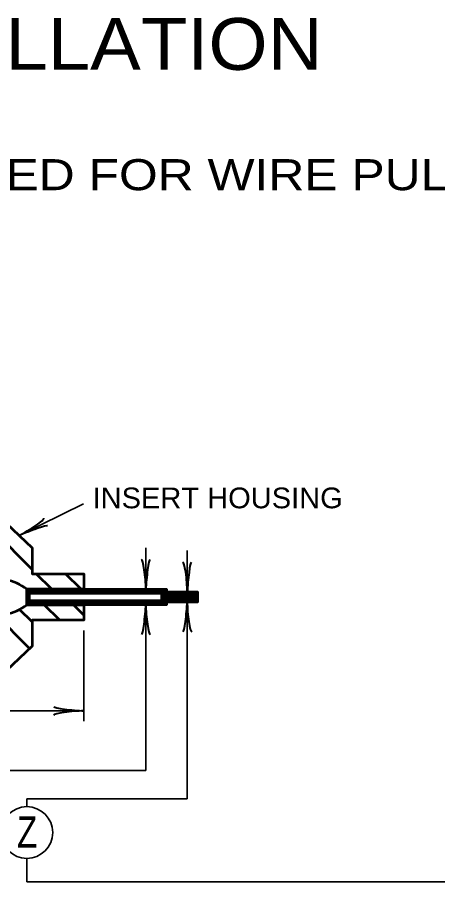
# Model space of a CAD drawing. Extents: x -1 to 679, y 0 to 440.
# Drawn here: x 139.2 to 179.8, y 135.8 to 219.2 of the extents above; entities that cross this region are included whole.
import ezdxf
from ezdxf.enums import TextEntityAlignment as Align

# ---------------------------------------------------------------- set-up
doc = ezdxf.new("R2010")
doc.units = 0
doc.header["$LTSCALE"] = 0.8
doc.layers.add('1', color=7, linetype='Continuous', lineweight=53)

msp = doc.modelspace()

# ---------------------------------------------------------------- linework, layer by layer
at = {"layer": '1', "lineweight": 35}
for p, q in [((139.3878, 169.1993), (145.6044, 172.2589)), ((151.6378, 164.0118), (151.6378, 168.0118)), ((155.6378, 163.7618), (155.6378, 167.7618)), ((151.6378, 162.5118), (151.6378, 146.5118)), ((155.6378, 162.7618), (155.6378, 143.7618)), ((145.6378, 160.0118), (145.6378, 151.2618)), ((122.6378, 152.2618), (145.6378, 152.2618)), ((151.6378, 146.5118), (134.6378, 146.5118)), ((155.6378, 143.7618), (140.1378, 143.7618)), ((140.1378, 143.7618), (140.1378, 143.0118)), ((140.1378, 138.0118), (140.1378, 135.7618)), ((140.1378, 135.7618), (223.051, 135.7618))]:
    msp.add_line(p, q, dxfattribs=at)
at = {"layer": '1'}
for p, q in [((140.6378, 165.9284), (136.1795, 170.3868)), ((142.5545, 164.0118), (141.0545, 165.5118)), ((145.3829, 164.0118), (143.8829, 165.5118)), ((140.1378, 164.0118), (145.6378, 164.0118)), ((140.1378, 163.9463), (140.2032, 164.0118)), ((140.1378, 163.8049), (140.3447, 164.0118)), ((140.1378, 163.6635), (140.4861, 164.0118)), ((140.1378, 163.5221), (140.6275, 164.0118)), ((140.4722, 163.6368), (140.1378, 163.9711)), ((140.3878, 163.5797), (140.1378, 163.8297)), ((140.3878, 163.4382), (140.1378, 163.6882)), ((140.1378, 163.3807), (140.3878, 163.6307)), ((140.6136, 163.6368), (140.2386, 164.0118)), ((140.755, 163.6368), (140.38, 164.0118)), ((140.3939, 163.6368), (140.7689, 164.0118)), ((140.8965, 163.6368), (140.5215, 164.0118)), ((140.5353, 163.6368), (140.9103, 164.0118)), ((141.0379, 163.6368), (140.6629, 164.0118)), ((140.6768, 163.6368), (141.0518, 164.0118)), ((141.1793, 163.6368), (140.8043, 164.0118)), ((140.8183, 163.6368), (141.1933, 164.0118)), ((141.3208, 163.6368), (140.9458, 164.0118)), ((140.9597, 163.6368), (141.3347, 164.0118)), ((141.4622, 163.6368), (141.0872, 164.0118)), ((141.1011, 163.6368), (141.4761, 164.0118)), ((141.6036, 163.6368), (141.2286, 164.0118)), ((141.2425, 163.6368), (141.6175, 164.0118)), ((141.745, 163.6368), (141.37, 164.0118)), ((141.3839, 163.6368), (141.7589, 164.0118)), ((141.8864, 163.6368), (141.5114, 164.0118)), ((141.5253, 163.6368), (141.9003, 164.0118)), ((142.0278, 163.6368), (141.6528, 164.0118)), ((141.6668, 163.6368), (142.0418, 164.0118)), ((142.1693, 163.6368), (141.7943, 164.0118)), ((141.8082, 163.6368), (142.1832, 164.0118)), ((142.3107, 163.6368), (141.9357, 164.0118)), ((141.9496, 163.6368), (142.3246, 164.0118)), ((142.4521, 163.6368), (142.0771, 164.0118)), ((142.091, 163.6368), (142.466, 164.0118)), ((142.5935, 163.6368), (142.2185, 164.0118)), ((142.2324, 163.6368), (142.6074, 164.0118)), ((142.7349, 163.6368), (142.3599, 164.0118)), ((142.3738, 163.6368), (142.7488, 164.0118)), ((142.8763, 163.6368), (142.5013, 164.0118)), ((142.5153, 163.6368), (142.8903, 164.0118)), ((143.0178, 163.6368), (142.6428, 164.0118)), ((142.6567, 163.6368), (143.0317, 164.0118)), ((143.1592, 163.6368), (142.7842, 164.0118)), ((142.7981, 163.6368), (143.1731, 164.0118)), ((143.3006, 163.6368), (142.9256, 164.0118)), ((142.9395, 163.6368), (143.3145, 164.0118)), ((143.4421, 163.6368), (143.0671, 164.0118)), ((143.081, 163.6368), (143.456, 164.0118)), ((143.5835, 163.6368), (143.2085, 164.0118)), ((143.2224, 163.6368), (143.5974, 164.0118)), ((143.7249, 163.6368), (143.3499, 164.0118)), ((143.3638, 163.6368), (143.7388, 164.0118)), ((143.8663, 163.6368), (143.4913, 164.0118)), ((143.5052, 163.6368), (143.8802, 164.0118)), ((144.0077, 163.6368), (143.6327, 164.0118)), ((143.6467, 163.6368), (144.0217, 164.0118)), ((144.1492, 163.6368), (143.7742, 164.0118)), ((143.7881, 163.6368), (144.1631, 164.0118)), ((144.2906, 163.6368), (143.9156, 164.0118)), ((143.9295, 163.6368), (144.3045, 164.0118)), ((144.432, 163.6368), (144.057, 164.0118)), ((144.0709, 163.6368), (144.4459, 164.0118)), ((144.5734, 163.6368), (144.1984, 164.0118)), ((144.2123, 163.6368), (144.5873, 164.0118)), ((144.7148, 163.6368), (144.3398, 164.0118)), ((144.3537, 163.6368), (144.7287, 164.0118)), ((144.8562, 163.6368), (144.4812, 164.0118)), ((144.4952, 163.6368), (144.8702, 164.0118)), ((144.9977, 163.6368), (144.6227, 164.0118)), ((144.6366, 163.6368), (145.0116, 164.0118)), ((145.1391, 163.6368), (144.7641, 164.0118)), ((144.778, 163.6368), (145.153, 164.0118)), ((145.2805, 163.6368), (144.9055, 164.0118)), ((144.9194, 163.6368), (145.2944, 164.0118)), ((145.4219, 163.6368), (145.0469, 164.0118)), ((145.0608, 163.6368), (145.4358, 164.0118)), ((145.5633, 163.6368), (145.1883, 164.0118)), ((145.2022, 163.6368), (145.5772, 164.0118)), ((145.7047, 163.6368), (145.3297, 164.0118)), ((145.3437, 163.6368), (145.7187, 164.0118)), ((145.8462, 163.6368), (145.4712, 164.0118)), ((145.4851, 163.6368), (145.8601, 164.0118)), ((145.9877, 163.6368), (145.6127, 164.0118)), ((145.6266, 163.6368), (146.0016, 164.0118)), ((146.1291, 163.6368), (145.7541, 164.0118)), ((145.768, 163.6368), (146.143, 164.0118)), ((146.2705, 163.6368), (145.8955, 164.0118)), ((145.9094, 163.6368), (146.2844, 164.0118)), ((146.4119, 163.6368), (146.0369, 164.0118)), ((146.0508, 163.6368), (146.4258, 164.0118)), ((146.5533, 163.6368), (146.1783, 164.0118)), ((146.1923, 163.6368), (146.5673, 164.0118)), ((146.6947, 163.6368), (146.3197, 164.0118)), ((146.3337, 163.6368), (146.7087, 164.0118)), ((146.8362, 163.6368), (146.4612, 164.0118)), ((146.4751, 163.6368), (146.8501, 164.0118)), ((146.9776, 163.6368), (146.6026, 164.0118)), ((146.6165, 163.6368), (146.9915, 164.0118)), ((147.119, 163.6368), (146.744, 164.0118)), ((146.7579, 163.6368), (147.1329, 164.0118)), ((147.2604, 163.6368), (146.8854, 164.0118)), ((146.8993, 163.6368), (147.2743, 164.0118)), ((147.4018, 163.6368), (147.0268, 164.0118)), ((147.0408, 163.6368), (147.4158, 164.0118)), ((147.5433, 163.6368), (147.1683, 164.0118)), ((147.1822, 163.6368), (147.5572, 164.0118)), ((147.6847, 163.6368), (147.3097, 164.0118)), ((147.3236, 163.6368), (147.6986, 164.0118)), ((147.8261, 163.6368), (147.4511, 164.0118)), ((147.465, 163.6368), (147.84, 164.0118)), ((147.9675, 163.6368), (147.5925, 164.0118)), ((147.6064, 163.6368), (147.9814, 164.0118)), ((148.1089, 163.6368), (147.7339, 164.0118)), ((147.7478, 163.6368), (148.1228, 164.0118)), ((148.2503, 163.6368), (147.8753, 164.0118)), ((147.8893, 163.6368), (148.2643, 164.0118)), ((148.3918, 163.6368), (148.0168, 164.0118)), ((148.0307, 163.6368), (148.4057, 164.0118)), ((148.5332, 163.6368), (148.1582, 164.0118)), ((148.1722, 163.6368), (148.5472, 164.0118)), ((148.6747, 163.6368), (148.2997, 164.0118)), ((148.3136, 163.6368), (148.6886, 164.0118)), ((148.8161, 163.6368), (148.4411, 164.0118)), ((148.455, 163.6368), (148.83, 164.0118)), ((148.9575, 163.6368), (148.5825, 164.0118)), ((148.5964, 163.6368), (148.9714, 164.0118)), ((149.0989, 163.6368), (148.7239, 164.0118)), ((148.7378, 163.6368), (149.1128, 164.0118)), ((149.2403, 163.6368), (148.8653, 164.0118)), ((148.8792, 163.6368), (149.2542, 164.0118)), ((149.3817, 163.6368), (149.0067, 164.0118)), ((149.0207, 163.6368), (149.3957, 164.0118)), ((149.5232, 163.6368), (149.1482, 164.0118)), ((149.1621, 163.6368), (149.5371, 164.0118)), ((149.6646, 163.6368), (149.2896, 164.0118)), ((149.3035, 163.6368), (149.6785, 164.0118)), ((149.806, 163.6368), (149.431, 164.0118)), ((149.4449, 163.6368), (149.8199, 164.0118)), ((149.9474, 163.6368), (149.5724, 164.0118)), ((149.5863, 163.6368), (149.9613, 164.0118)), ((150.0888, 163.6368), (149.7138, 164.0118)), ((149.7277, 163.6368), (150.1027, 164.0118)), ((150.2302, 163.6368), (149.8552, 164.0118)), ((149.8692, 163.6368), (150.2442, 164.0118)), ((150.3717, 163.6368), (149.9967, 164.0118)), ((150.0106, 163.6368), (150.3856, 164.0118)), ((150.5131, 163.6368), (150.1381, 164.0118)), ((150.152, 163.6368), (150.527, 164.0118)), ((150.6545, 163.6368), (150.2795, 164.0118)), ((150.2934, 163.6368), (150.6684, 164.0118)), ((150.7959, 163.6368), (150.4209, 164.0118)), ((150.4348, 163.6368), (150.8098, 164.0118)), ((150.9374, 163.6368), (150.5624, 164.0118)), ((150.5762, 163.6368), (150.9512, 164.0118)), ((151.0788, 163.6368), (150.7038, 164.0118)), ((150.7177, 163.6368), (151.0927, 164.0118)), ((151.2202, 163.6368), (150.8452, 164.0118)), ((150.8592, 163.6368), (151.2342, 164.0118)), ((151.3617, 163.6368), (150.9867, 164.0118)), ((151.0006, 163.6368), (151.3756, 164.0118)), ((151.5031, 163.6368), (151.1281, 164.0118)), ((151.142, 163.6368), (151.517, 164.0118)), ((151.6445, 163.6368), (151.2695, 164.0118)), ((151.2834, 163.6368), (151.6584, 164.0118)), ((151.7859, 163.6368), (151.4109, 164.0118)), ((151.4248, 163.6368), (151.7998, 164.0118)), ((151.9273, 163.6368), (151.5523, 164.0118)), ((151.5662, 163.6368), (151.9412, 164.0118)), ((152.0687, 163.6368), (151.6937, 164.0118)), ((151.7077, 163.6368), (152.0827, 164.0118)), ((152.2102, 163.6368), (151.8352, 164.0118)), ((151.8491, 163.6368), (152.2241, 164.0118)), ((152.3516, 163.6368), (151.9766, 164.0118)), ((151.9905, 163.6368), (152.3655, 164.0118)), ((152.493, 163.6368), (152.118, 164.0118)), ((152.1319, 163.6368), (152.5069, 164.0118)), ((152.6344, 163.6368), (152.2594, 164.0118)), ((152.2733, 163.6368), (152.6483, 164.0118)), ((152.7758, 163.6368), (152.4008, 164.0118)), ((152.4147, 163.6368), (152.7897, 164.0118)), ((152.9172, 163.6368), (152.5422, 164.0118)), ((152.5562, 163.6368), (152.9312, 164.0118)), ((153.0587, 163.6368), (152.6837, 164.0118)), ((152.6976, 163.6368), (153.0726, 164.0118)), ((154.0751, 162.7618), (152.8251, 164.0118)), ((152.839, 163.6368), (153.214, 164.0118)), ((152.8454, 162.5118), (154.0954, 163.7618)), ((154.2165, 162.7618), (152.9665, 164.0118)), ((152.9804, 163.6368), (153.3554, 164.0118)), ((152.9868, 162.5118), (154.2368, 163.7618)), ((154.358, 162.7618), (153.108, 164.0118)), ((153.1219, 163.6368), (153.4969, 164.0118)), ((153.1283, 162.5118), (154.3783, 163.7618)), ((153.1378, 163.5112), (153.6378, 164.0112)), ((153.1378, 163.3698), (153.6378, 163.8698)), ((153.1378, 163.2284), (153.6712, 163.7618)), ((153.1378, 163.087), (153.8126, 163.7618)), ((153.1378, 162.9456), (153.954, 163.7618)), ((154.4994, 162.7618), (153.2494, 164.0118)), ((153.2697, 162.5118), (154.5197, 163.7618)), ((153.6378, 163.7647), (153.3908, 164.0118)), ((153.6378, 163.9062), (153.5323, 164.0118)), ((154.6408, 162.7618), (153.6408, 163.7618)), ((153.6611, 162.7618), (154.6611, 163.7618)), ((154.7823, 162.7618), (153.7823, 163.7618)), ((153.8025, 162.7618), (154.8025, 163.7618)), ((154.9237, 162.7618), (153.9237, 163.7618)), ((153.9439, 162.7618), (154.9439, 163.7618)), ((155.0651, 162.7618), (154.0651, 163.7618)), ((154.0853, 162.7618), (155.0853, 163.7618)), ((155.2065, 162.7618), (154.2065, 163.7618)), ((154.2267, 162.7618), (155.2267, 163.7618)), ((155.3479, 162.7618), (154.3479, 163.7618)), ((154.3682, 162.7618), (155.3682, 163.7618)), ((155.4893, 162.7618), (154.4893, 163.7618)), ((154.5096, 162.7618), (155.5096, 163.7618)), ((155.6308, 162.7618), (154.6308, 163.7618)), ((154.651, 162.7618), (155.651, 163.7618)), ((155.7722, 162.7618), (154.7722, 163.7618)), ((154.7925, 162.7618), (155.7925, 163.7618)), ((155.9136, 162.7618), (154.9136, 163.7618)), ((154.9339, 162.7618), (155.9339, 163.7618)), ((156.055, 162.7618), (155.055, 163.7618)), ((155.0753, 162.7618), (156.0753, 163.7618)), ((156.1964, 162.7618), (155.1964, 163.7618)), ((155.2167, 162.7618), (156.2167, 163.7618)), ((156.3378, 162.7618), (155.3378, 163.7618)), ((155.3582, 162.7618), (156.3582, 163.7618)), ((156.4793, 162.7618), (155.4793, 163.7618)), ((155.4996, 162.7618), (156.4996, 163.7618)), ((156.6207, 162.7618), (155.6207, 163.7618)), ((155.641, 162.7618), (156.6378, 163.7586)), ((156.6378, 162.886), (155.7621, 163.7618)), ((156.6378, 163.0275), (155.9036, 163.7618)), ((156.6378, 163.1689), (156.045, 163.7618)), ((156.6378, 163.3103), (156.1864, 163.7618)), ((156.6378, 163.4518), (156.3278, 163.7618)), ((156.6378, 163.5932), (156.4692, 163.7618)), ((156.6378, 163.7346), (156.6107, 163.7618)), ((140.3878, 163.2968), (140.1378, 163.5468)), ((140.1378, 163.2392), (140.3878, 163.4892)), ((140.3878, 163.1554), (140.1378, 163.4054)), ((140.1378, 163.0977), (140.3878, 163.3477)), ((140.3878, 163.014), (140.1378, 163.264)), ((140.1378, 162.9563), (140.3878, 163.2063)), ((140.7487, 162.5118), (140.1378, 163.1226)), ((140.1378, 162.8149), (140.3878, 163.0649)), ((140.6072, 162.5118), (140.1378, 162.9812)), ((140.1378, 162.6735), (140.3878, 162.9235)), ((140.1378, 162.5321), (140.4925, 162.8868)), ((140.4658, 162.5118), (140.1378, 162.8397)), ((140.2589, 162.5118), (140.6339, 162.8868)), ((140.4003, 162.5118), (140.7753, 162.8868)), ((140.8901, 162.5118), (140.5151, 162.8868)), ((140.5418, 162.5118), (140.9168, 162.8868)), ((141.0315, 162.5118), (140.6565, 162.8868)), ((140.6832, 162.5118), (141.0582, 162.8868)), ((141.1729, 162.5118), (140.7979, 162.8868)), ((140.8246, 162.5118), (141.1996, 162.8868)), ((141.3143, 162.5118), (140.9393, 162.8868)), ((140.966, 162.5118), (141.341, 162.8868)), ((141.4557, 162.5118), (141.0807, 162.8868)), ((141.1074, 162.5118), (141.4824, 162.8868)), ((141.5972, 162.5118), (141.2222, 162.8868)), ((141.2488, 162.5118), (141.6238, 162.8868)), ((141.7386, 162.5118), (141.3636, 162.8868)), ((141.3903, 162.5118), (141.7653, 162.8868)), ((141.88, 162.5118), (141.505, 162.8868)), ((141.5317, 162.5118), (141.9067, 162.8868)), ((142.0215, 162.5118), (141.6465, 162.8868)), ((141.6731, 162.5118), (142.0481, 162.8868)), ((142.1629, 162.5118), (141.7879, 162.8868)), ((141.8145, 162.5118), (142.1895, 162.8868)), ((142.3043, 162.5118), (141.9293, 162.8868)), ((141.956, 162.5118), (142.331, 162.8868)), ((142.4458, 162.5118), (142.0708, 162.8868)), ((142.0974, 162.5118), (142.4724, 162.8868)), ((142.5872, 162.5118), (142.2122, 162.8868)), ((142.2388, 162.5118), (142.6138, 162.8868)), ((142.7286, 162.5118), (142.3536, 162.8868)), ((142.3802, 162.5118), (142.7552, 162.8868)), ((142.87, 162.5118), (142.495, 162.8868)), ((142.5217, 162.5118), (142.8967, 162.8868)), ((143.0114, 162.5118), (142.6364, 162.8868)), ((142.6631, 162.5118), (143.0381, 162.8868)), ((143.1528, 162.5118), (142.7778, 162.8868)), ((142.8045, 162.5118), (143.1795, 162.8868)), ((143.2943, 162.5118), (142.9193, 162.8868)), ((142.9459, 162.5118), (143.3209, 162.8868)), ((143.4357, 162.5118), (143.0607, 162.8868)), ((143.0873, 162.5118), (143.4623, 162.8868)), ((143.5771, 162.5118), (143.2021, 162.8868)), ((143.2287, 162.5118), (143.6037, 162.8868)), ((143.7185, 162.5118), (143.3435, 162.8868)), ((143.3702, 162.5118), (143.7452, 162.8868)), ((143.8599, 162.5118), (143.4849, 162.8868)), ((143.5116, 162.5118), (143.8866, 162.8868)), ((144.0013, 162.5118), (143.6263, 162.8868)), ((143.653, 162.5118), (144.028, 162.8868)), ((144.1428, 162.5118), (143.7678, 162.8868)), ((143.7944, 162.5118), (144.1694, 162.8868)), ((144.2842, 162.5118), (143.9092, 162.8868)), ((143.9358, 162.5118), (144.3108, 162.8868)), ((144.4256, 162.5118), (144.0506, 162.8868)), ((144.0772, 162.5118), (144.4522, 162.8868)), ((144.5671, 162.5118), (144.1921, 162.8868)), ((144.2187, 162.5118), (144.5937, 162.8868)), ((144.7085, 162.5118), (144.3335, 162.8868)), ((144.3601, 162.5118), (144.7351, 162.8868)), ((144.8499, 162.5118), (144.4749, 162.8868)), ((144.5016, 162.5118), (144.8766, 162.8868)), ((144.9913, 162.5118), (144.6163, 162.8868)), ((144.643, 162.5118), (145.018, 162.8868)), ((145.1327, 162.5118), (144.7577, 162.8868)), ((144.7844, 162.5118), (145.1594, 162.8868)), ((145.2742, 162.5118), (144.8992, 162.8868)), ((144.9258, 162.5118), (145.3008, 162.8868)), ((145.4156, 162.5118), (145.0406, 162.8868)), ((145.0673, 162.5118), (145.4423, 162.8868)), ((145.557, 162.5118), (145.182, 162.8868)), ((145.2087, 162.5118), (145.5837, 162.8868)), ((145.6984, 162.5118), (145.3234, 162.8868)), ((145.3501, 162.5118), (145.7251, 162.8868)), ((145.8398, 162.5118), (145.4648, 162.8868)), ((145.4915, 162.5118), (145.8665, 162.8868)), ((145.9812, 162.5118), (145.6062, 162.8868)), ((145.6329, 162.5118), (146.0079, 162.8868)), ((146.1227, 162.5118), (145.7477, 162.8868)), ((145.7743, 162.5118), (146.1493, 162.8868)), ((146.2641, 162.5118), (145.8891, 162.8868)), ((145.9158, 162.5118), (146.2908, 162.8868)), ((146.4055, 162.5118), (146.0305, 162.8868)), ((146.0572, 162.5118), (146.4322, 162.8868)), ((146.5469, 162.5118), (146.1719, 162.8868)), ((146.1986, 162.5118), (146.5736, 162.8868)), ((146.6883, 162.5118), (146.3133, 162.8868)), ((146.34, 162.5118), (146.715, 162.8868)), ((146.8297, 162.5118), (146.4547, 162.8868)), ((146.4814, 162.5118), (146.8564, 162.8868)), ((146.9712, 162.5118), (146.5962, 162.8868)), ((146.6228, 162.5118), (146.9978, 162.8868)), ((147.1127, 162.5118), (146.7377, 162.8868)), ((146.7643, 162.5118), (147.1393, 162.8868)), ((147.2541, 162.5118), (146.8791, 162.8868)), ((146.9057, 162.5118), (147.2807, 162.8868)), ((147.3955, 162.5118), (147.0205, 162.8868)), ((147.0472, 162.5118), (147.4222, 162.8868)), ((147.5369, 162.5118), (147.1619, 162.8868)), ((147.1886, 162.5118), (147.5636, 162.8868)), ((147.6783, 162.5118), (147.3033, 162.8868)), ((147.33, 162.5118), (147.705, 162.8868)), ((147.8197, 162.5118), (147.4447, 162.8868)), ((147.4714, 162.5118), (147.8464, 162.8868)), ((147.9612, 162.5118), (147.5862, 162.8868)), ((147.6128, 162.5118), (147.9878, 162.8868)), ((148.1026, 162.5118), (147.7276, 162.8868)), ((147.7542, 162.5118), (148.1292, 162.8868)), ((148.244, 162.5118), (147.869, 162.8868)), ((147.8957, 162.5118), (148.2707, 162.8868)), ((148.3854, 162.5118), (148.0104, 162.8868)), ((148.0371, 162.5118), (148.4121, 162.8868)), ((148.5268, 162.5118), (148.1518, 162.8868)), ((148.1785, 162.5118), (148.5535, 162.8868)), ((148.6683, 162.5118), (148.2933, 162.8868)), ((148.3199, 162.5118), (148.6949, 162.8868)), ((148.8097, 162.5118), (148.4347, 162.8868)), ((148.4613, 162.5118), (148.8363, 162.8868)), ((148.9511, 162.5118), (148.5761, 162.8868)), ((148.6027, 162.5118), (148.9777, 162.8868)), ((149.0925, 162.5118), (148.7175, 162.8868)), ((148.7442, 162.5118), (149.1192, 162.8868)), ((149.2339, 162.5118), (148.8589, 162.8868)), ((148.8856, 162.5118), (149.2606, 162.8868)), ((149.3753, 162.5118), (149.0003, 162.8868)), ((149.027, 162.5118), (149.402, 162.8868)), ((149.5168, 162.5118), (149.1418, 162.8868)), ((149.1684, 162.5118), (149.5434, 162.8868)), ((149.6582, 162.5118), (149.2832, 162.8868)), ((149.3098, 162.5118), (149.6848, 162.8868)), ((149.7997, 162.5118), (149.4247, 162.8868)), ((149.4512, 162.5118), (149.8262, 162.8868)), ((149.9411, 162.5118), (149.5661, 162.8868)), ((149.5927, 162.5118), (149.9677, 162.8868)), ((150.0825, 162.5118), (149.7075, 162.8868)), ((149.7342, 162.5118), (150.1092, 162.8868)), ((150.2239, 162.5118), (149.8489, 162.8868)), ((149.8756, 162.5118), (150.2506, 162.8868)), ((150.3653, 162.5118), (149.9903, 162.8868)), ((150.017, 162.5118), (150.392, 162.8868)), ((150.5067, 162.5118), (150.1317, 162.8868)), ((150.1584, 162.5118), (150.5334, 162.8868)), ((150.6482, 162.5118), (150.2732, 162.8868)), ((150.2998, 162.5118), (150.6748, 162.8868)), ((150.7896, 162.5118), (150.4146, 162.8868)), ((150.4412, 162.5118), (150.8162, 162.8868)), ((150.931, 162.5118), (150.556, 162.8868)), ((150.5827, 162.5118), (150.9577, 162.8868)), ((151.0724, 162.5118), (150.6974, 162.8868)), ((150.7241, 162.5118), (151.0991, 162.8868)), ((151.2138, 162.5118), (150.8388, 162.8868)), ((150.8655, 162.5118), (151.2405, 162.8868)), ((151.3552, 162.5118), (150.9802, 162.8868)), ((151.0069, 162.5118), (151.3819, 162.8868)), ((151.4967, 162.5118), (151.1217, 162.8868)), ((151.1483, 162.5118), (151.5233, 162.8868)), ((151.6381, 162.5118), (151.2631, 162.8868)), ((151.2897, 162.5118), (151.6647, 162.8868)), ((151.7795, 162.5118), (151.4045, 162.8868)), ((151.4312, 162.5118), (151.8062, 162.8868)), ((151.9209, 162.5118), (151.5459, 162.8868)), ((151.5726, 162.5118), (151.9476, 162.8868)), ((152.0624, 162.5118), (151.6874, 162.8868)), ((151.714, 162.5118), (152.089, 162.8868)), ((152.2038, 162.5118), (151.8288, 162.8868)), ((151.8554, 162.5118), (152.2304, 162.8868)), ((152.3452, 162.5118), (151.9702, 162.8868)), ((151.9969, 162.5118), (152.3719, 162.8868)), ((152.4867, 162.5118), (152.1117, 162.8868)), ((152.1383, 162.5118), (152.5133, 162.8868)), ((152.6281, 162.5118), (152.2531, 162.8868)), ((152.2798, 162.5118), (152.6548, 162.8868)), ((152.7695, 162.5118), (152.3945, 162.8868)), ((152.4212, 162.5118), (152.7962, 162.8868)), ((152.9109, 162.5118), (152.5359, 162.8868)), ((152.5626, 162.5118), (152.9376, 162.8868)), ((153.0523, 162.5118), (152.6773, 162.8868)), ((152.704, 162.5118), (153.079, 162.8868)), ((153.1937, 162.5118), (152.8187, 162.8868)), ((153.3352, 162.5118), (152.9602, 162.8868)), ((153.4766, 162.5118), (153.1016, 162.8868)), ((153.9337, 162.7618), (153.1378, 163.5576)), ((153.7922, 162.7618), (153.1378, 163.4162)), ((153.6508, 162.7618), (153.1378, 163.2747)), ((153.6378, 162.6333), (153.1378, 163.1333)), ((153.618, 162.5118), (153.1378, 162.9919)), ((155.7824, 162.7618), (156.6378, 163.6172)), ((155.9238, 162.7618), (156.6378, 163.4758)), ((156.0652, 162.7618), (156.6378, 163.3343)), ((156.2067, 162.7618), (156.6378, 163.1929)), ((156.3481, 162.7618), (156.6378, 163.0515)), ((156.4895, 162.7618), (156.6378, 162.9101)), ((140.6378, 160.8569), (139.4365, 162.0582)), ((140.3244, 162.5118), (140.1378, 162.6983)), ((140.183, 162.5118), (140.1378, 162.5569)), ((145.6378, 162.5118), (140.1378, 162.5118)), ((143.3114, 161.0118), (141.8114, 162.5118)), ((145.6378, 161.5138), (144.6399, 162.5118)), ((153.4111, 162.5118), (153.6378, 162.7385)), ((153.5525, 162.5118), (153.6378, 162.5971)), ((156.6309, 162.7618), (156.6378, 162.7687)), ((140.39, 158.2763), (137.0987, 161.5676))]:
    msp.add_line(p, q, dxfattribs=at)
for points in [[(135.8878, 164.7086), (135.8878, 170.3868), (138.1378, 170.3868), (140.6378, 168.0118), (140.6378, 165.5118), (145.6378, 165.5118), (145.6378, 164.0118), (140.1378, 164.0118)], [(140.1378, 162.5118), (145.6378, 162.5118), (145.6378, 161.0118), (140.6378, 161.0118), (140.6378, 158.5118), (138.1378, 156.1368), (135.8878, 156.1368)]]:
    msp.add_lwpolyline(points, dxfattribs=at)
for points in [[(140.1378, 162.5118), (140.1378, 164.0118), (145.6378, 164.0118), (153.6378, 164.0118), (153.6378, 163.7618), (156.6378, 163.7618), (156.6378, 162.7618), (153.6378, 162.7618), (153.6378, 162.5118), (145.6378, 162.5118)], [(140.3878, 162.8868), (140.3878, 163.6368), (153.1378, 163.6368), (153.1378, 162.8868)]]:
    msp.add_lwpolyline(points, close=True, dxfattribs=at)
at = {"layer": '1', "lineweight": 35}
msp.add_circle((140.1378, 140.5118), 2.5, dxfattribs=at)
at = {"layer": '1'}
for centre, start, end in [((137.3878, 160.5481), 51.55204, 109.82604), ((137.3878, 165.9754), 250.17396, 308.44796)]:
    msp.add_arc(centre, 4.4226, start, end, dxfattribs=at)
at = {"layer": '1', "lineweight": 40}
for centre, major_axis, ratio, start_param, end_param in [((140.2449, 169.929), (-1.5332, -0.9286), 0.122415, 0.8963533, 3.1415927), ((140.4866, 169.5042), (-1.6535, -0.618), 0.07063, 3.1407148, 5.41811), ((151.3615, 165.1029), (0.1562, -1.7857), 0.122415, 0.8963533, 3.1415927), ((151.3615, 165.1029), (0.1562, -1.7857), 0.122415, 0.8963533, 3.1415927), ((151.8494, 165.1323), (-0.1757, -1.7565), 0.07063, 3.1407148, 5.41811), ((151.8494, 165.1323), (-0.1757, -1.7565), 0.07063, 3.1407148, 5.41811), ((155.3615, 164.8529), (0.1562, -1.7857), 0.122415, 0.8963533, 3.1415927), ((155.8494, 164.8823), (-0.1757, -1.7565), 0.07063, 3.1407148, 5.41811), ((151.4262, 161.3912), (0.1757, 1.7565), 0.07063, 3.1407148, 5.41811), ((151.4262, 161.3912), (0.1757, 1.7565), 0.07063, 3.1407148, 5.41811), ((151.9141, 161.4206), (-0.1562, 1.7857), 0.122415, 0.8963533, 3.1415927), ((151.9141, 161.4206), (-0.1562, 1.7857), 0.122415, 0.8963533, 3.1415927), ((155.4262, 161.6412), (0.1757, 1.7565), 0.07063, 3.1407148, 5.41811), ((155.9141, 161.6706), (-0.1562, 1.7857), 0.122415, 0.8963533, 3.1415927), ((144.5466, 151.9855), (1.7857, 0.1562), 0.122415, 0.8963533, 3.1415927), ((144.5173, 152.4734), (1.7565, -0.1757), 0.07063, 3.1407148, 5.41811)]:
    msp.add_ellipse(centre, major_axis=major_axis, ratio=ratio, start_param=start_param, end_param=end_param, dxfattribs=at)

# ---------------------------------------------------------------- texts
at = {"layer": '1', "width": 1.1}
msp.add_text('BOX INSTALLATION', height=5, dxfattribs=at).set_placement((133.7752, 214.1718), align=Align.CENTER)
at = {"layer": '1'}
for s, height, width, p in [('( ) WHEREVER JUNCTION BOXES ARE USED FOR WIRE PULLING PURPOSES ONLY.', 3, 1.2, (41.5177, 202.5465)), ('INSERT HOUSING', 2, 1.05, (146.4861, 171.8282)), ('Z', 3, 0.8, (139.1877, 139.0644))]:
    msp.add_text(s, height=height, dxfattribs=dict(at, width=width)).set_placement(p)

doc.saveas('drawing.dxf')
